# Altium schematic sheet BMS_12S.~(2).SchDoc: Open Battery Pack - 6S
size A3; Author: Morgane Vallée; Revision: 1.0; SheetNumber: 3; SheetTotal: 4
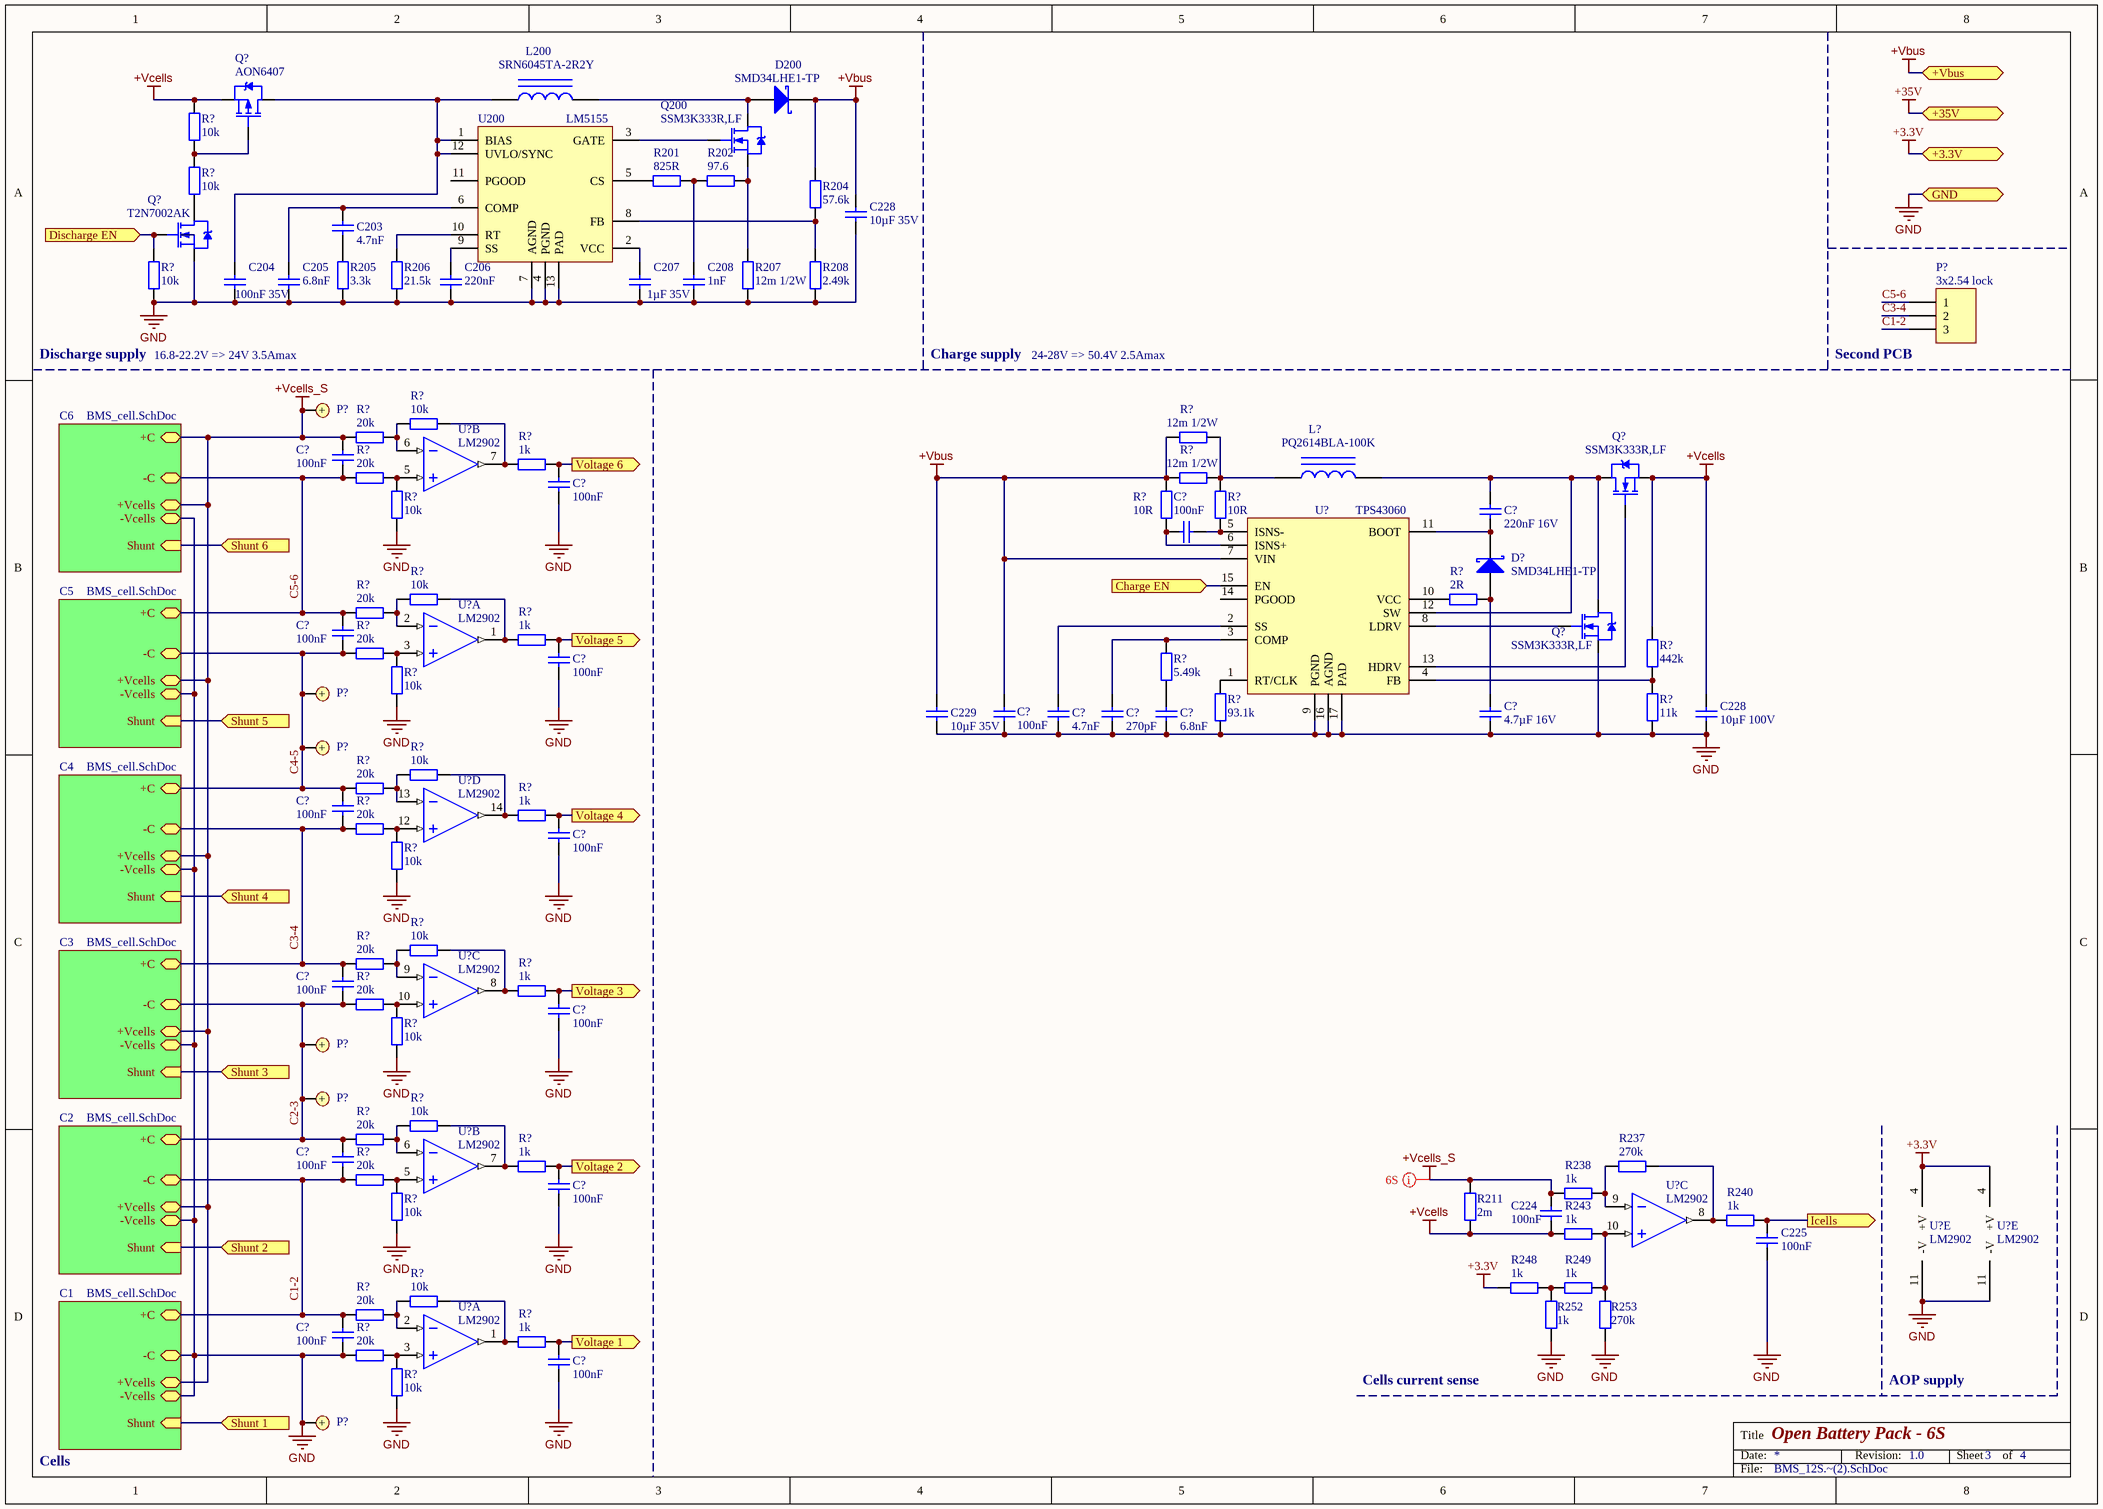
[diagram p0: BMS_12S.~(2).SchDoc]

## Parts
(Parts that share a designator on the sheet are numbered #1, #2 ... from top to bottom, then left to right.)
C203  4.7nF  [C0603]
C204  100nF 35V  [C0603]
C205  6.8nF  [C0603]
C206  220nF  [C0603]
C207  1µF 35V  [C0805]
C208  1nF  [C0603]
C224  100nF  [C0603]
C225  100nF  [C0603]
C228#1  10µF 35V  [C0603]
C228#2  10µF 100V  [C0603]
C229  10µF 35V  [C0603]
C?#1  100nF  [C0603]
C?#2  100nF  [C0603]
C?#3  220nF 16V  [C0603]
C?#4  100nF  [C0603]
C?#5  100nF  [C0603]
C?#6  100nF  [C0603]
C?#7  4.7nF  [C0603]
C?#8  270pF  [C0603]
C?#9  6.8nF  [C0603]
C?#10  4.7µF 16V  [C0805]
C?#11  100nF  [C0603]
C?#12  100nF  [C0603]
C?#13  100nF  [C0603]
C?#14  100nF  [C0603]
C?#15  100nF  [C0603]
C?#16  100nF  [C0603]
C?#17  100nF  [C0603]
C?#18  100nF  [C0603]
C?#19  100nF  [C0603]
D200  SMD34LHE1-TP  [SOD-123H]
D?  SMD34LHE1-TP  [SOD-123H]
L200  SRN6045TA-2R2Y  [SELF_SMD_8x8]
L?  PQ2614BLA-100K  [SELF_SMD_8x8]
P?#1  3x2.54 lock  [MOLEX KK 0022272031]
P?#2  Bat+  [Keystone 241]  (value not drawn)
P?#3  Bat+  [Keystone 241]  (value not drawn)
P?#4  Bat+  [Keystone 241]  (value not drawn)
P?#5  Bat+  [Keystone 241]  (value not drawn)
P?#6  Bat+  [Keystone 241]  (value not drawn)
P?#7  Bat+  [Keystone 241]  (value not drawn)
Q200  SSM3K333R,LF  [TI SOT-23-3 DBZ]
Q?#1  AON6407  [DIODES SOT-23-3]
Q?#2  T2N7002AK  [DIODES SOT-23-3]
Q?#3  SSM3K333R,LF  [TI SOT-23-3 DBZ]
Q?#4  SSM3K333R,LF  [TI SOT-23-3 DBZ]
R201  825R  [R0603]
R202  97.6  [R0603]
R204  57.6k  [R0603]
R205  3.3k  [R0603]
R206  21.5k  [R0603]
R207  12m 1/2W  [R1206]
R208  2.49k  [R0603]
R211  2m  [R1206]
R237  270k  [R0603]
R238  1k  [R0603]
R240  1k  [R0603]
R243  1k  [R0603]
R248  1k  [R0603]
R249  1k  [R0603]
R252  1k  [R0603]
R253  270k  [R0603]
R?#1  10k  [R0603]
R?#2  10k  [R0603]
R?#3  10k  [R0603]
R?#4  10k  [R0603]
R?#5  20k  [R0603]
R?#6  12m 1/2W  [R1206]
R?#7  1k  [R0603]
R?#8  20k  [R0603]
R?#9  10k  [R0603]
R?#10  10R  [R0603]
R?#11  12m 1/2W  [R1206]
R?#12  10R  [R0603]
R?#13  10k  [R0603]
R?#14  20k  [R0603]
R?#15  2R  [R0603]
R?#16  1k  [R0603]
R?#17  20k  [R0603]
R?#18  10k  [R0603]
R?#19  442k  [R0603]
R?#20  5.49k  [R0603]
R?#21  93.1k  [R0603]
R?#22  11k  [R0603]
R?#23  10k  [R0603]
R?#24  20k  [R0603]
R?#25  1k  [R0603]
R?#26  20k  [R0603]
R?#27  10k  [R0603]
R?#28  10k  [R0603]
R?#29  20k  [R0603]
R?#30  1k  [R0603]
R?#31  20k  [R0603]
R?#32  10k  [R0603]
R?#33  10k  [R0603]
R?#34  20k  [R0603]
R?#35  1k  [R0603]
R?#36  20k  [R0603]
R?#37  10k  [R0603]
R?#38  10k  [R0603]
R?#39  20k  [R0603]
R?#40  1k  [R0603]
R?#41  20k  [R0603]
R?#42  10k  [R0603]
U200  LM5155  [TI WSON-12]
U?#1  LM2902  [Atmel SO-14 14S1]  (part B of 5)
U?#2  LM2902  [Atmel SO-14 14S1]  (part A of 5)
U?#3  TPS43060  [TI WQFN-16 RGH]
U?#4  LM2902  [Atmel SO-14 14S1]  (part D of 5)
U?#5  LM2902  [Atmel SO-14 14S1]  (part C of 5)
U?#6  LM2902  [Atmel SO-14 14S1]  (part B of 5)
U?#7  LM2902  [Atmel SO-14 14S1]  (part C of 5)
U?#8  LM2902  [Atmel SO-14 14S1]  (part E of 5)
U?#9  LM2902  [Atmel SO-14 14S1]  (part E of 5)
U?#10  LM2902  [Atmel SO-14 14S1]  (part A of 5)

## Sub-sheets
C1 = BMS_cell.SchDoc: -C, +C, +Vcells, -Vcells, Shunt (in)
C2 = BMS_cell.SchDoc: -C, +C, +Vcells, -Vcells, Shunt (in)
C3 = BMS_cell.SchDoc: -C, +C, +Vcells, -Vcells, Shunt (in)
C4 = BMS_cell.SchDoc: -C, +C, +Vcells, -Vcells, Shunt (in)
C5 = BMS_cell.SchDoc: -C, +C, +Vcells, -Vcells, Shunt (in)
C6 = BMS_cell.SchDoc: -C, +C, +Vcells, -Vcells, Shunt (in)

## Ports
+3.3V, +35V, +Vbus, Charge EN (in), Discharge EN (in), GND, Icells (out), Shunt 1 (in), Shunt 2 (in), Shunt 3 (in), Shunt 4 (in), Shunt 5 (in), Shunt 6 (in), Voltage 1 (out), Voltage 2 (out), Voltage 3 (out), Voltage 4 (out), Voltage 5 (out), Voltage 6 (out)

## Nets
+3.3V: R248.2 U?#8.4(+V) U?#9.4(+V) ; port +3.3V
+Vbus: C228#1.1 C229.1 C?#11.2 D200.3(K) R204.2 R?#6.2 R?#10.1 R?#11.2 U?#3.7(VIN) ; port +Vbus
+Vcells: C224.2 C228#2.1 Q?#1.2(S) Q?#3.2(S) R211.1 R243.2 R?#1.2 R?#19.2
+Vcells_S: C224.1 C?#1.1 P?#2.1 R211.2 R238.1 R?#5.1 ; sheet C1/+Vcells, sheet C2/+Vcells, sheet C3/+Vcells, sheet C4/+Vcells, sheet C5/+Vcells, sheet C6/+C, sheet C6/+Vcells
GND: C204.2 C205.2 C206.2 C207.2 C208.2 C225.2 C228#1.2 C228#2.2 C229.2 C?#2.2 C?#6.2 C?#7.2 C?#8.2 C?#9.2 C?#10.2 C?#11.1 C?#13.2 C?#15.2 C?#17.2 C?#18.2 C?#19.2 P?#7.1 Q?#2.2(S) Q?#4.2(S) R205.1 R206.1 R207.1 R208.1 R252.2 R253.1 R?#3.1 R?#9.2 R?#18.2 R?#21.1 R?#22.1 R?#27.2 R?#32.2 R?#37.2 R?#41.2 R?#42.2 U200.4(PGND) U200.7(AGND) U200.13(PAD) U?#3.9(PGND) U?#3.16(AGND) U?#3.17(PAD) U?#8.11(-V) U?#9.11(-V) ; port GND, sheet C1/-C, sheet C1/-Vcells, sheet C2/-Vcells, sheet C3/-Vcells, sheet C4/-Vcells, sheet C5/-Vcells, sheet C6/-Vcells
C1-2: C?#16.2 C?#18.1 P?#1.3 R?#36.2 R?#39.1 ; sheet C1/+C, sheet C2/-C
C2-3: C?#14.2 C?#16.1 P?#5.1 P?#6.1 R?#31.2 R?#34.1 ; sheet C2/+C, sheet C3/-C
C3-4: C?#12.2 C?#14.1 P?#1.2 R?#26.2 R?#29.1 ; sheet C3/+C, sheet C4/-C
C4-5: C?#5.2 C?#12.1 P?#3.1 P?#4.1 R?#17.2 R?#24.1 ; sheet C4/+C, sheet C5/-C
C5-6: C?#1.2 C?#5.1 P?#1.1 R?#8.2 R?#14.1 ; sheet C5/+C, sheet C6/-C
Charge EN: U?#3.15(EN) ; port Charge EN
Discharge EN: Q?#2.1(G) R?#3.2 ; port Discharge EN
Icells: C225.1 R240.1 ; port Icells
Shunt 1: port Shunt 1, sheet C1/Shunt
Shunt 2: port Shunt 2, sheet C2/Shunt
Shunt 3: port Shunt 3, sheet C3/Shunt
Shunt 4: port Shunt 4, sheet C4/Shunt
Shunt 5: port Shunt 5, sheet C5/Shunt
Shunt 6: port Shunt 6, sheet C6/Shunt
Voltage 1: C?#19.1 R?#40.1 ; port Voltage 1
Voltage 2: C?#17.1 R?#35.1 ; port Voltage 2
Voltage 3: C?#15.1 R?#30.1 ; port Voltage 3
Voltage 4: C?#13.1 R?#25.1 ; port Voltage 4
Voltage 5: C?#6.1 R?#16.1 ; port Voltage 5
Voltage 6: C?#2.1 R?#7.1 ; port Voltage 6
NetC203_1: C203.1 C205.1 U200.6(COMP)
NetC203_2: C203.2 R205.2
NetC204_1: C204.1 L200.1 Q?#1.3(D) U200.1(BIAS) U200.12(UVLO/SYNC)
NetC206_1: C206.1 U200.9(SS)
NetC207_1: C207.1 U200.2(VCC)
NetC208_1: C208.1 R201.1 R202.2
NetC?#3_1: C?#3.1 L?.2 Q?#3.3(D) Q?#4.3(D) U?#3.12(SW)
NetC?#3_2: C?#3.2 D?.3(K) U?#3.11(BOOT)
NetC?#4_1: C?#4.1 R?#12.2 U?#3.5(ISNS-)
NetC?#4_2: C?#4.2 R?#10.2 U?#3.6(ISNS+)
NetC?#7_1: C?#7.1 U?#3.2(SS)
NetC?#8_1: C?#8.1 R?#20.2 U?#3.3(COMP)
NetC?#9_1: C?#9.1 R?#20.1
NetC?#10_1: C?#10.1 D?.1(A) R?#15.1
NetD200_1: D200.1(A) L200.2 Q200.3(D)
NetL?_1: L?.1 R?#6.1 R?#11.1 R?#12.1
NetQ200_1: Q200.1(G) U200.3(GATE)
NetQ200_2: Q200.2(S) R202.1 R207.2
NetQ?#1_1: Q?#1.1(G) R?#1.1 R?#2.2
NetQ?#2_3: Q?#2.3(D) R?#2.1
NetQ?#3_1: Q?#3.1(G) U?#3.13(HDRV)
NetQ?#4_1: Q?#4.1(G) U?#3.8(LDRV)
NetR201_2: R201.2 U200.5(CS)
NetR204_1: R204.1 R208.2 U200.8(FB)
NetR206_2: R206.2 U200.10(RT)
NetR237_1: R237.1 R240.2 U?#7.8(OUT)
NetR237_2: R237.2 R238.2 U?#7.9(IN-)
NetR243_1: R243.1 R249.1 R253.2 U?#7.10(IN+)
NetR248_1: R248.1 R249.2 R252.1
NetR?#4_1: R?#4.1 R?#5.2 U?#1.6(IN-)
NetR?#4_2: R?#4.2 R?#7.2 U?#1.7(OUT)
NetR?#8_1: R?#8.1 R?#9.1 U?#1.5(IN+)
NetR?#13_1: R?#13.1 R?#14.2 U?#2.2(IN-)
NetR?#13_2: R?#13.2 R?#16.2 U?#2.1(OUT)
NetR?#15_2: R?#15.2 U?#3.10(VCC)
NetR?#17_1: R?#17.1 R?#18.1 U?#2.3(IN+)
NetR?#19_1: R?#19.1 R?#22.2 U?#3.4(FB)
NetR?#21_2: R?#21.2 U?#3.1(RT/CLK)
NetR?#23_1: R?#23.1 R?#24.2 U?#4.13(IN-)
NetR?#23_2: R?#23.2 R?#25.2 U?#4.14(OUT)
NetR?#26_1: R?#26.1 R?#27.1 U?#4.12(IN+)
NetR?#28_1: R?#28.1 R?#29.2 U?#5.9(IN-)
NetR?#28_2: R?#28.2 R?#30.2 U?#5.8(OUT)
NetR?#31_1: R?#31.1 R?#32.1 U?#5.10(IN+)
NetR?#33_1: R?#33.1 R?#34.2 U?#6.6(IN-)
NetR?#33_2: R?#33.2 R?#35.2 U?#6.7(OUT)
NetR?#36_1: R?#36.1 R?#37.1 U?#6.5(IN+)
NetR?#38_1: R?#38.1 R?#39.2 U?#10.2(IN-)
NetR?#38_2: R?#38.2 R?#40.2 U?#10.1(OUT)
NetR?#41_1: R?#41.1 R?#42.1 U?#10.3(IN+)

Not connected (* = marked no-connect by the designer): U200 11(PGOOD); U?#3 14(PGOOD)

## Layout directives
net class 6S: +Vcells_S

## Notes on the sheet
- Discharge supply
- 16.8-22.2V => 24V 3.5Amax
- Charge supply
- 24-28V => 50.4V 2.5Amax
- (near P?#1) Second PCB
- Cells current sense
- AOP supply
- Cells

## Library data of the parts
C203-C208 C224 C225 C228#1 C228#2 C229 C?#1-C?#19 = Cap: Capacitor
D200 D? = Diode BAT17
L200 L? = Inductor Iron: Magnetic-Core Inductor
P?#1 = Header 3: Header, 3-Pin
P?#2-P?#7 = Bat+: Battery contact +
Q200 Q?#2-Q?#4 = MOSFET_N
Q?#1 = MOSFET_P
R201 R202 R204-R208 R211 R237 R238 R240 R243 R248 R249 R252 R253 R?#1-R?#42 = Res2: Resistor
U200 = LM5155: 2.2-MHz Wide Input Nonsynchronous Boost, SEPIC, Flyback Controller
U?#1 U?#2 U?#4-U?#10 = LM2902: Low-power quad operational amplifiers
U?#3 = TPS43060: Low Quiescent Current Synchronous Boost  DC-DC Controller With Wide VIN Range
